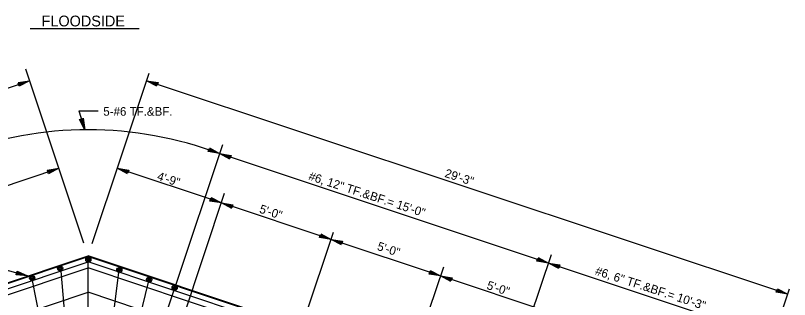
# Model space of a CAD drawing. Extents: x 6 to 106, y 3 to 74.
# Drawn here: x 38.04 to 71.53, y 59.53 to 71.84 of the extents above; entities that cross this region are included whole.
import ezdxf

# ---------------------------------------------------------------- set-up
doc = ezdxf.new("R2010")
doc.units = 0
for name, color, linetype in [('Level 22', 7, 'Continuous'), ('Level 25', 7, 'Continuous'), ('Level 50', 7, 'Continuous')]:
    doc.layers.add(name, color=color, linetype=linetype)

msp = doc.modelspace()

# ---------------------------------------------------------------- linework, layer by layer
at = {"layer": 'Level 22'}
for p, q in [((38.672, 71.278), (43.386, 71.278)), ((40.786, 67.703), (41.612, 67.703)), ((40.786, 67.703), (41.044, 66.884)), ((35.712, 61.347), (38.565, 60.552)), ((40.704, 53.118), (40.01, 60.765)), ((41.575, 53.152), (42.518, 60.713)), ((40.241, 52.945), (38.783, 60.35)), ((42.02, 52.945), (43.799, 60.28))]:
    msp.add_line(p, q, dxfattribs=at)
msp.add_arc((41.18, 50.691), 16.194, 69.4208, 110.5793, dxfattribs=at)
at = {"layer": 'Level 25'}
for p, q in [((40.997, 61.975), (38.485, 69.511)), ((41.359, 61.959), (43.821, 69.346)), ((10.902, 59.764), (38.651, 69.013)), ((71.459, 59.764), (43.71, 69.013)), ((44.975, 60.159), (47.006, 66.251)), ((61.103, 61.108), (46.873, 65.851)), ((35.409, 63.716), (39.916, 65.219)), ((46.952, 63.716), (42.445, 65.219)), ((45.239, 58.579), (47.091, 64.133)), ((51.695, 62.135), (46.952, 63.716)), ((49.972, 56.967), (51.802, 62.456)), ((56.438, 60.554), (51.695, 62.135)), ((14.561, 52.551), (41.18, 61.424)), ((20.588, 54.527), (41.19, 61.394)), ((61.773, 54.527), (41.171, 61.394)), ((67.8, 52.551), (41.18, 61.424)), ((59.205, 55.416), (61.228, 61.482)), ((14.835, 52.378), (41.18, 61.16)), ((41.18, 53.204), (41.18, 61.18)), ((67.623, 52.346), (41.18, 61.16)), ((70.827, 57.866), (61.103, 61.108)), ((20.736, 54.082), (41.18, 60.897)), ((61.625, 54.082), (41.18, 60.897)), ((55.943, 59.067), (56.57, 60.949)), ((61.182, 58.973), (56.438, 60.554)), ((42.501, 52.737), (44.907, 59.956)), ((68.618, 51.24), (71.534, 59.988)), ((9.584, 49.31), (41.18, 59.843)), ((66.501, 51.403), (41.18, 59.843))]:
    msp.add_line(p, q, dxfattribs=at)
at = {"layer": 'Level 50'}
for p, q in [((38.651, 69.013), (38.651, 69.013)), ((43.71, 69.013), (43.71, 69.013)), ((38.519, 68.969), (38.519, 68.969)), ((43.842, 68.969), (43.842, 68.969)), ((41.002, 67.016), (41.002, 67.016)), ((41.044, 66.884), (41.044, 66.884)), ((46.743, 65.9), (46.743, 65.9)), ((46.873, 65.851), (46.873, 65.851)), ((46.873, 65.851), (46.873, 65.851)), ((47.004, 65.807), (47.004, 65.807)), ((39.784, 65.175), (39.784, 65.175)), ((39.916, 65.219), (39.916, 65.219)), ((42.445, 65.219), (42.445, 65.219)), ((42.577, 65.175), (42.577, 65.175)), ((46.82, 63.76), (46.82, 63.76)), ((46.952, 63.716), (46.952, 63.716)), ((46.952, 63.716), (46.952, 63.716)), ((47.083, 63.673), (47.083, 63.673)), ((51.563, 62.179), (51.563, 62.179)), ((51.695, 62.135), (51.695, 62.135)), ((51.695, 62.135), (51.695, 62.135)), ((51.827, 62.091), (51.827, 62.091)), ((60.971, 61.151), (60.971, 61.151)), ((61.103, 61.108), (61.103, 61.108)), ((61.103, 61.108), (61.103, 61.108)), ((61.234, 61.064), (61.234, 61.064)), ((38.432, 60.589), (38.432, 60.589)), ((38.565, 60.552), (38.565, 60.552)), ((56.307, 60.598), (56.307, 60.598)), ((56.438, 60.554), (56.438, 60.554)), ((56.438, 60.554), (56.438, 60.554)), ((56.57, 60.51), (56.57, 60.51)), ((71.328, 59.807), (71.328, 59.807)), ((71.328, 59.807), (71.328, 59.807)), ((71.459, 59.764), (71.459, 59.764)), ((71.459, 59.764), (71.459, 59.764))]:
    msp.add_line(p, q, dxfattribs=at)
for points in [[(38.151, 68.934), (38.651, 69.013), (38.204, 68.777), (38.159, 68.911), (38.519, 68.969), (38.216, 68.809), (38.187, 68.895), (38.393, 68.927), (38.227, 68.841), (38.216, 68.877), (38.261, 68.883)], [(44.157, 68.777), (43.71, 69.013), (44.209, 68.934), (44.165, 68.8), (43.842, 68.969), (44.181, 68.915), (44.152, 68.829), (43.968, 68.927), (44.152, 68.897), (44.14, 68.862), (44.1, 68.883)], [(40.973, 67.384), (41.044, 66.884), (40.815, 67.334), (40.95, 67.377), (41.002, 67.016), (40.847, 67.322), (40.933, 67.349), (40.962, 67.143), (40.879, 67.31), (40.914, 67.321), (40.92, 67.275)], [(46.435, 66.104), (46.873, 65.851), (46.377, 65.949), (46.426, 66.081), (46.743, 65.9), (46.406, 65.966), (46.438, 66.051), (46.618, 65.947), (46.435, 65.984), (46.448, 66.019), (46.488, 65.995)], [(47.319, 65.615), (46.873, 65.851), (47.372, 65.772), (47.327, 65.638), (47.004, 65.807), (47.343, 65.753), (47.314, 65.667), (47.131, 65.765), (47.314, 65.735), (47.303, 65.699), (47.262, 65.721)], [(39.416, 65.139), (39.916, 65.219), (39.469, 64.982), (39.424, 65.117), (39.784, 65.175), (39.48, 65.014), (39.452, 65.1), (39.658, 65.133), (39.492, 65.047), (39.48, 65.082), (39.526, 65.089)], [(42.892, 64.982), (42.445, 65.219), (42.945, 65.139), (42.9, 65.005), (42.577, 65.175), (42.916, 65.121), (42.887, 65.035), (42.703, 65.133), (42.887, 65.102), (42.875, 65.067), (42.835, 65.089)], [(46.505, 63.953), (46.952, 63.716), (46.452, 63.796), (46.497, 63.93), (46.82, 63.76), (46.481, 63.814), (46.51, 63.9), (46.694, 63.802), (46.51, 63.833), (46.522, 63.868), (46.562, 63.846)], [(47.399, 63.48), (46.952, 63.716), (47.451, 63.637), (47.406, 63.503), (47.083, 63.673), (47.422, 63.619), (47.393, 63.533), (47.21, 63.63), (47.393, 63.6), (47.382, 63.565), (47.341, 63.587)], [(51.248, 62.371), (51.695, 62.135), (51.196, 62.215), (51.24, 62.349), (51.563, 62.179), (51.224, 62.233), (51.253, 62.319), (51.437, 62.221), (51.253, 62.252), (51.265, 62.287), (51.305, 62.265)], [(52.142, 61.899), (51.695, 62.135), (52.194, 62.056), (52.15, 61.922), (51.827, 62.091), (52.166, 62.038), (52.137, 61.952), (51.953, 62.049), (52.137, 62.019), (52.125, 61.984), (52.085, 62.005)], [(60.656, 61.344), (61.103, 61.108), (60.604, 61.187), (60.648, 61.321), (60.971, 61.151), (60.632, 61.205), (60.661, 61.291), (60.845, 61.194), (60.661, 61.224), (60.673, 61.259), (60.713, 61.237)], [(61.55, 60.871), (61.103, 61.108), (61.602, 61.028), (61.557, 60.894), (61.234, 61.064), (61.573, 61.01), (61.545, 60.924), (61.361, 61.022), (61.545, 60.991), (61.533, 60.956), (61.492, 60.978)], [(38.107, 60.766), (38.565, 60.552), (38.063, 60.606), (38.101, 60.742), (38.432, 60.589), (38.09, 60.626), (38.115, 60.714), (38.303, 60.625), (38.118, 60.646), (38.128, 60.682), (38.17, 60.662)], [(55.991, 60.79), (56.438, 60.554), (55.939, 60.633), (55.984, 60.768), (56.307, 60.598), (55.968, 60.652), (55.997, 60.738), (56.18, 60.64), (55.997, 60.671), (56.008, 60.706), (56.049, 60.684)], [(56.885, 60.318), (56.438, 60.554), (56.938, 60.475), (56.893, 60.341), (56.57, 60.51), (56.909, 60.456), (56.88, 60.37), (56.696, 60.468), (56.88, 60.438), (56.869, 60.402), (56.828, 60.424)], [(71.012, 60), (71.459, 59.764), (70.96, 59.843), (71.005, 59.977), (71.328, 59.807), (70.989, 59.861), (71.017, 59.947), (71.201, 59.85), (71.017, 59.88), (71.029, 59.915), (71.07, 59.894)], [(71.012, 60), (71.459, 59.764), (70.96, 59.843), (71.005, 59.977), (71.328, 59.807), (70.989, 59.861), (71.017, 59.947), (71.201, 59.85), (71.017, 59.88), (71.029, 59.915), (71.07, 59.894)]]:
    msp.add_lwpolyline(points, dxfattribs=at)
for centre, radius in [((41.192, 61.255), 0.113), ((41.192, 61.255), 0.0703), ((39.973, 60.884), 0.113), ((41.192, 61.255), 0.0281), ((39.973, 60.884), 0.0703), ((39.973, 60.884), 0.0281), ((42.535, 60.804), 0.113), ((42.535, 60.804), 0.0703), ((42.535, 60.804), 0.0281), ((38.763, 60.459), 0.113), ((38.763, 60.459), 0.0703), ((38.763, 60.459), 0.0281), ((43.825, 60.397), 0.113), ((43.825, 60.397), 0.0703), ((43.825, 60.397), 0.0281), ((44.929, 60.044), 0.113), ((44.929, 60.044), 0.0703), ((44.929, 60.044), 0.0281)]:
    msp.add_circle(centre, radius, dxfattribs=at)

# ---------------------------------------------------------------- texts
at = {"layer": 'Level 22'}
for s, height, p in [('FLOODSIDE', 0.4667, (39.17, 71.366)), ('5-#6 TF.&BF.', 0.37333, (41.84, 67.495))]:
    msp.add_text(s, height=height, dxfattribs=at).set_placement(p)
for s, height, p in [('4\'-9"', 0.3733, (44.139, 64.722)), ('#6, 12" TF.&BF.= 15\'-0"', 0.37333, (50.693, 64.726)), ('29\'-3"', 0.3733, (56.584, 64.85)), ('5\'-0"', 0.3733, (48.564, 63.3)), ('5\'-0"', 0.3733, (53.661, 61.686)), ('#6, 6" TF.&BF.= 10\'-3"', 0.37333, (63.092, 60.616)), ('5\'-0"', 0.3733, (58.403, 59.995))]:
    msp.add_text(s, height=height, rotation=342, dxfattribs=at).set_placement(p)

doc.saveas('drawing.dxf')
